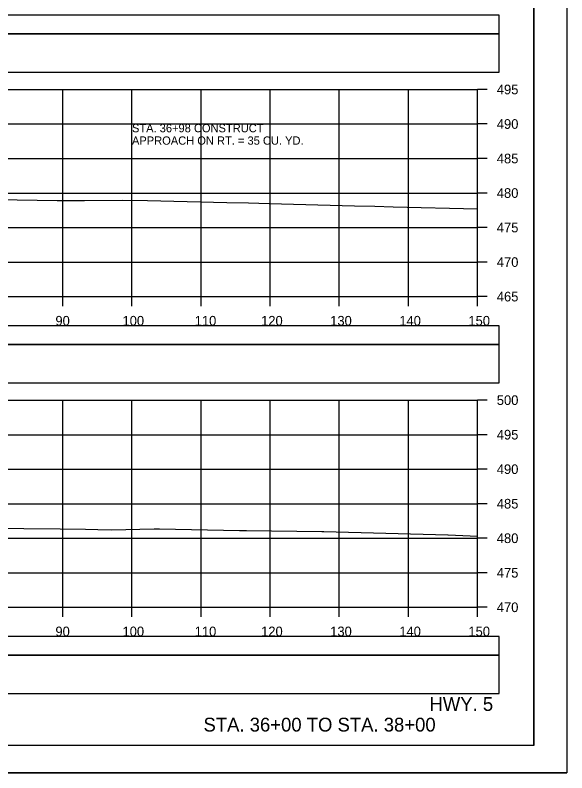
# Model space of a CAD drawing. Extents: x 1371057 to 1372761, y 380005 to 390517.
# Drawn here: x 1371644 to 1371723.8, y 381071.8 to 381181.5 of the extents above; entities that cross this region are included whole.
import ezdxf

# ---------------------------------------------------------------- set-up
doc = ezdxf.new("R2010")
doc.units = 0
for name, color, linetype in [('R_Axis', 7, 'Continuous'), ('R_Axis Annot', 7, 'Continuous'), ('R_Border', 7, 'Continuous'), ('R_Detour', 7, 'Continuous'), ('R_Dimension', 7, 'Continuous'), ('R_Draft', 7, 'Continuous'), ('R_Exist Surface', 7, 'Continuous'), ('R_Grid', 7, 'Continuous'), ('R_No Plot', 7, 'Continuous'), ('R_Water Annot', 7, 'Continuous')]:
    doc.layers.add(name, color=color, linetype=linetype)

msp = doc.modelspace()

# ---------------------------------------------------------------- linework, layer by layer
at = {"layer": 'R_Axis'}
for p, q in [((1371710.87, 381140.75), (1371710.87, 381170.75)), ((1371712.27, 381170.75), (1371710.87, 381170.75)), ((1371712.27, 381165.75), (1371710.87, 381165.75)), ((1371712.27, 381160.75), (1371710.87, 381160.75)), ((1371712.27, 381155.75), (1371710.87, 381155.75)), ((1371712.27, 381150.75), (1371710.87, 381150.75)), ((1371712.27, 381145.75), (1371710.87, 381145.75)), ((1371410.87, 381140.75), (1371710.87, 381140.75)), ((1371650.87, 381139.35), (1371650.87, 381140.75)), ((1371660.87, 381139.35), (1371660.87, 381140.75)), ((1371670.87, 381139.35), (1371670.87, 381140.75)), ((1371680.87, 381139.35), (1371680.87, 381140.75)), ((1371690.87, 381139.35), (1371690.87, 381140.75)), ((1371700.87, 381139.35), (1371700.87, 381140.75)), ((1371710.87, 381139.35), (1371710.87, 381140.75)), ((1371712.27, 381140.75), (1371710.87, 381140.75)), ((1371710.87, 381095.75), (1371710.87, 381125.75)), ((1371712.27, 381125.75), (1371710.87, 381125.75)), ((1371712.27, 381120.75), (1371710.87, 381120.75)), ((1371712.27, 381115.75), (1371710.87, 381115.75)), ((1371712.27, 381110.75), (1371710.87, 381110.75)), ((1371712.27, 381105.75), (1371710.87, 381105.75)), ((1371712.27, 381100.75), (1371710.87, 381100.75)), ((1371410.87, 381095.75), (1371710.87, 381095.75)), ((1371650.87, 381094.35), (1371650.87, 381095.75)), ((1371660.87, 381094.35), (1371660.87, 381095.75)), ((1371670.87, 381094.35), (1371670.87, 381095.75)), ((1371680.87, 381094.35), (1371680.87, 381095.75)), ((1371690.87, 381094.35), (1371690.87, 381095.75)), ((1371700.87, 381094.35), (1371700.87, 381095.75)), ((1371710.87, 381094.35), (1371710.87, 381095.75)), ((1371712.27, 381095.75), (1371710.87, 381095.75))]:
    msp.add_line(p, q, dxfattribs=at)
at = {"layer": 'R_Border'}
for q in [(1371719.05, 381281.21), (1371402.87, 381075.75)]:
    msp.add_line((1371719.05, 381075.75), q, dxfattribs=at)
at = {"layer": 'R_Detour'}
for points in [[(1371407.72, 381178.8), (1371714.03, 381178.8), (1371714.03, 381181.5), (1371407.72, 381181.5)], [(1371407.72, 381133.8), (1371714.03, 381133.8), (1371714.03, 381136.5), (1371407.72, 381136.5)], [(1371407.72, 381088.8), (1371714.03, 381088.8), (1371714.03, 381091.5), (1371407.72, 381091.5)]]:
    msp.add_lwpolyline(points, close=True, dxfattribs=at)
at = {"layer": 'R_Dimension'}
for points in [[(1371407.72, 381173.27), (1371714.03, 381173.27), (1371714.03, 381178.8), (1371407.72, 381178.8)], [(1371407.72, 381128.27), (1371714.03, 381128.27), (1371714.03, 381133.8), (1371407.72, 381133.8)], [(1371407.72, 381083.27), (1371714.03, 381083.27), (1371714.03, 381088.8), (1371407.72, 381088.8)]]:
    msp.add_lwpolyline(points, close=True, dxfattribs=at)
at = {"layer": 'R_Exist Surface'}
for points in [[(1371631.54, 381155.02), (1371644.25, 381154.77), (1371650.06, 381154.65), (1371654.02, 381154.68), (1371659.54, 381154.74), (1371663.11, 381154.67), (1371674.62, 381154.39), (1371677.75, 381154.32), (1371680.74, 381154.25), (1371693.07, 381153.91), (1371696.02, 381153.86), (1371698.65, 381153.77), (1371710.87, 381153.47)], [(1371639.93, 381107.23), (1371650.49, 381107.13), (1371654.12, 381107.06), (1371655.92, 381107.03), (1371657.92, 381106.97), (1371664.07, 381107.11), (1371664.63, 381107.12), (1371664.84, 381107.12), (1371676.44, 381106.86), (1371677.42, 381106.86), (1371688.34, 381106.74), (1371688.47, 381106.73), (1371688.63, 381106.73), (1371706.57, 381106.22), (1371706.62, 381106.22), (1371710.87, 381106.05)]]:
    msp.add_lwpolyline(points, dxfattribs=at)
at = {"layer": 'R_Grid'}
for p, q in [((1371410.87, 381170.75), (1371710.87, 381170.75)), ((1371650.87, 381140.75), (1371650.87, 381170.75)), ((1371660.87, 381140.75), (1371660.87, 381170.75)), ((1371670.87, 381140.75), (1371670.87, 381170.75)), ((1371680.87, 381140.75), (1371680.87, 381170.75)), ((1371690.87, 381140.75), (1371690.87, 381170.75)), ((1371700.87, 381140.75), (1371700.87, 381170.75)), ((1371710.87, 381140.75), (1371710.87, 381170.75)), ((1371410.87, 381165.75), (1371710.87, 381165.75)), ((1371410.87, 381160.75), (1371710.87, 381160.75)), ((1371410.87, 381155.75), (1371710.87, 381155.75)), ((1371410.87, 381150.75), (1371710.87, 381150.75)), ((1371410.87, 381145.75), (1371710.87, 381145.75)), ((1371410.87, 381140.75), (1371710.87, 381140.75)), ((1371410.87, 381125.75), (1371710.87, 381125.75)), ((1371650.87, 381095.75), (1371650.87, 381125.75)), ((1371660.87, 381095.75), (1371660.87, 381125.75)), ((1371670.87, 381095.75), (1371670.87, 381125.75)), ((1371680.87, 381095.75), (1371680.87, 381125.75)), ((1371690.87, 381095.75), (1371690.87, 381125.75)), ((1371700.87, 381095.75), (1371700.87, 381125.75)), ((1371710.87, 381095.75), (1371710.87, 381125.75)), ((1371410.87, 381120.75), (1371710.87, 381120.75)), ((1371410.87, 381115.75), (1371710.87, 381115.75)), ((1371410.87, 381110.75), (1371710.87, 381110.75)), ((1371410.87, 381105.75), (1371710.87, 381105.75)), ((1371410.87, 381100.75), (1371710.87, 381100.75)), ((1371410.87, 381095.75), (1371710.87, 381095.75))]:
    msp.add_line(p, q, dxfattribs=at)
at = {"layer": 'R_No Plot'}
msp.add_line((1371390.47, 381071.77), (1371723.8, 381071.77), dxfattribs=at)
for points in [[(1371390.46, 381285.1), (1371723.8, 381285.1), (1371723.8, 381071.77), (1371390.46, 381071.77)], [(1371636.79, 381281.21), (1371656.41, 381281.21), (1371656.41, 381271.33), (1371672.52, 381271.33), (1371695.72, 381271.33), (1371695.84, 381243.17), (1371719.05, 381243.17), (1371719.05, 381075.75), (1371402.87, 381075.75), (1371402.87, 381281.21)]]:
    msp.add_lwpolyline(points, close=True, dxfattribs=at)

# ---------------------------------------------------------------- texts
at = {"layer": 'R_Axis Annot'}
for s, p in [('495', (1371713.67, 381170.05)), ('490', (1371713.67, 381165.05)), ('485', (1371713.67, 381160.05)), ('480', (1371713.67, 381155.05)), ('475', (1371713.67, 381150.05)), ('470', (1371713.67, 381145.05)), ('465', (1371713.67, 381140.05)), ('90', (1371649.79, 381136.55)), ('100', (1371659.5, 381136.55)), ('110', (1371669.95, 381136.55)), ('120', (1371679.56, 381136.55)), ('130', (1371689.56, 381136.55)), ('140', (1371699.56, 381136.55)), ('150', (1371709.56, 381136.55)), ('500', (1371713.67, 381125.05)), ('495', (1371713.67, 381120.05)), ('490', (1371713.67, 381115.05)), ('485', (1371713.67, 381110.05)), ('480', (1371713.67, 381105.05)), ('475', (1371713.67, 381100.05)), ('470', (1371713.67, 381095.05)), ('90', (1371649.79, 381091.55)), ('100', (1371659.5, 381091.55)), ('110', (1371669.95, 381091.55)), ('120', (1371679.56, 381091.55)), ('130', (1371689.56, 381091.55)), ('140', (1371699.56, 381091.55)), ('150', (1371709.56, 381091.55))]:
    msp.add_text(s, height=1.4, dxfattribs=at).set_placement(p)
at = {"layer": 'R_Draft'}
for s, p in [('HWY. 5', (1371703.93, 381080.74)), ('STA. 36+00 TO STA. 38+00', (1371671.22, 381077.75))]:
    msp.add_text(s, height=2, dxfattribs=at).set_placement(p)
at = {"layer": 'R_Water Annot'}
for s, p in [('STA. 36+98 CONSTRUCT', (1371660.87, 381164.55)), ('APPROACH ON RT. = 35 CU. YD.', (1371660.87, 381162.75))]:
    msp.add_text(s, height=1.2, dxfattribs=at).set_placement(p)

doc.saveas('drawing.dxf')
